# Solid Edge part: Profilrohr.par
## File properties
Username: ahadarics
Dokumentum tartalom típus: 0
Author: ahadarics
Last saved by: ahadarics
Revision: 87
Sűrűség: 0,000 kg/m^3
Pontosság: 0,990
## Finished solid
Body 1: solid body, 6 faces, 6 edges, 0 vertices.
  Faces by surface: cone 2, cylinder 2, plane 2
  Edges by curve: circle 6
Bounding box of the edges (mm): 21.270 x 21.270 x 532.000, from (-10.635, -10.635, -21) to (10.635, 10.635, 511).
Cylindrical faces by radius (mm): R10 x1, R10.635 x1
Conical faces (half-angle, radius in mm at the cone's reference point): 15 deg R10.067 x2
Planar faces by outward normal: +z 1, -z 1
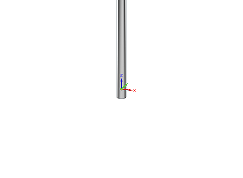
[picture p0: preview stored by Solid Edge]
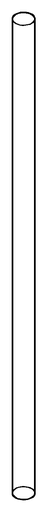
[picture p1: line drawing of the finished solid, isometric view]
